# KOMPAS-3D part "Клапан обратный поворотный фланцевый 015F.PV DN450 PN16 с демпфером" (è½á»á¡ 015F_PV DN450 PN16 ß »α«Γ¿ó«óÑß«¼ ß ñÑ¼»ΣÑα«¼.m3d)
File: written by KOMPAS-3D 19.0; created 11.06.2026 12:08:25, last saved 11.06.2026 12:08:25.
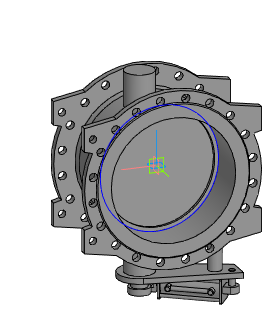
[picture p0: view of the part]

Document properties: Автор: Энергия; Полное имя файла: Z:\3.Личные\kachalov\001_3d для проектировщиков\5.5 Тип 015F.PV Клапан обратный поворотный с двумя эксцентриками\_stp_Клапан 015F.PV DN300-DN1200 с противовесом с демпфером\Клапан 015F_PV DN450 PN16 с противовесом с демпфером.m3d

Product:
- Part/product: Клапан обратный поворотный фланцевый 015F.PV DN450 PN16 с демпфером

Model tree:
1. Операция без истории:1
2. Сплайн:1
     Координата Y = 30; Координата Z = 225; Вес = 1; Координата X = 450; Координата Y = 89.2436; Координата Z = 225; Вес = 0.333333; Координата X = 450; Координата Y = 89.2436; Координата Z = -225; Вес = 0.333333; Координата Y = 30; Координата Z = -225; Вес = 1; Координата X = -450; Координата Y = -29.2436; Координата Z = -225; Вес = 0.333333; Координата X = -450; Координата Y = -29.2436; Координата Z = 225; Вес = 0.333333; Порядок = 4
